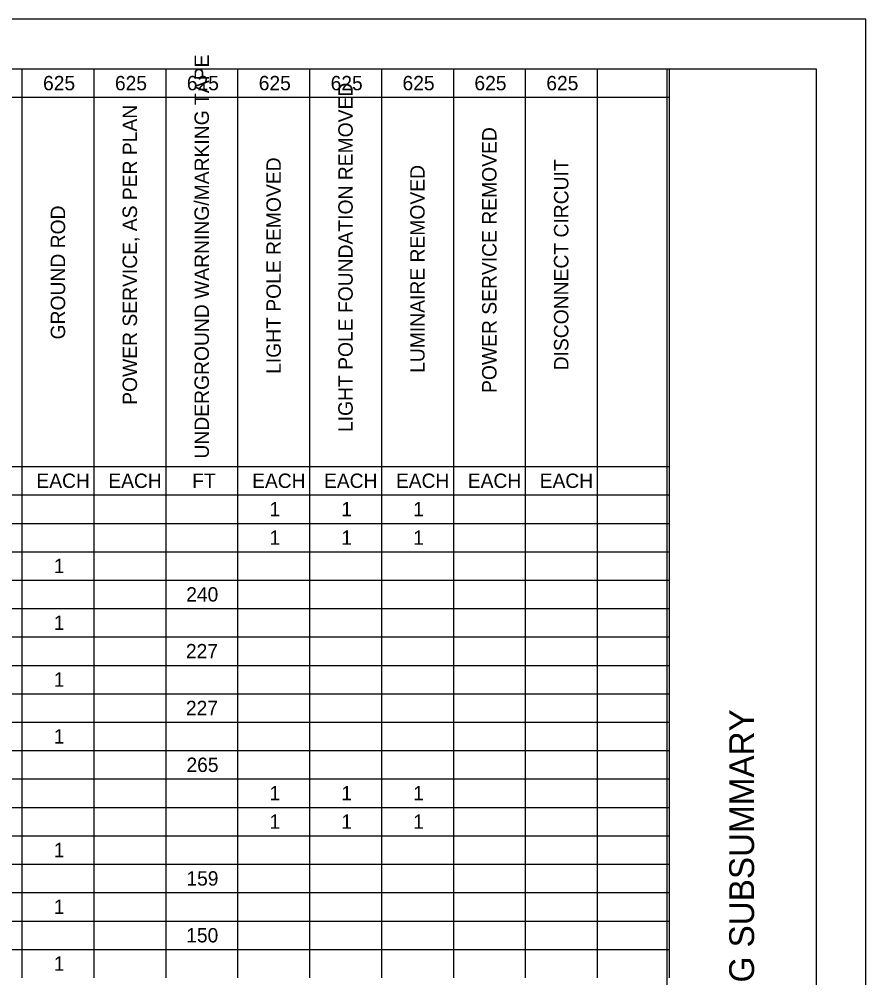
# Model space of a CAD drawing. Extents: x -1022.2 to -988.2, y -965.8 to -943.8.
# Drawn here: x -996.77 to -988.25, y -953.43 to -943.79 of the extents above; entities that cross this region are included whole.
import ezdxf

# ---------------------------------------------------------------- set-up
doc = ezdxf.new("R2010")
doc.units = 0
for name, color, linetype in [('Default', 7, 'Continuous'), ('SH_Border', 7, 'Continuous'), ('SH_Cut_Line', 7, 'Continuous'), ('SH_Data', 7, 'Continuous')]:
    doc.layers.add(name, color=color, linetype=linetype)

msp = doc.modelspace()

# ---------------------------------------------------------------- linework, layer by layer
at = {"layer": 'Default'}
for p, q in [((-998.1912, -944.2862), (-996.0201, -944.2862)), ((-996.7438, -944.2862), (-996.7438, -944.5719)), ((-996.0201, -944.2862), (-995.2964, -944.2862)), ((-996.0201, -944.2862), (-996.0201, -944.5719)), ((-995.2964, -944.2862), (-994.5726, -944.2862)), ((-995.2964, -944.2862), (-995.2964, -944.5719)), ((-994.5726, -944.2862), (-992.4015, -944.2862)), ((-994.5726, -944.2862), (-994.5726, -944.5719)), ((-993.8489, -944.2862), (-993.8489, -944.5719)), ((-993.1252, -944.2862), (-993.1252, -944.5719)), ((-992.4015, -944.2862), (-991.6778, -944.2862)), ((-992.4015, -944.2862), (-992.4015, -944.5719)), ((-991.6778, -944.2862), (-990.9541, -944.2862)), ((-991.6778, -944.2862), (-991.6778, -944.5719)), ((-990.9541, -944.2862), (-990.2303, -944.2862)), ((-990.9541, -944.2862), (-990.9541, -944.5719)), ((-990.2303, -944.2862), (-990.2303, -944.5719)), ((-998.1912, -944.5719), (-996.0201, -944.5719)), ((-996.7438, -944.5719), (-996.7438, -944.8577)), ((-996.0201, -944.5719), (-995.2964, -944.5719)), ((-996.0201, -944.5719), (-996.0201, -944.8577)), ((-995.2964, -944.5719), (-994.5726, -944.5719)), ((-995.2964, -944.5719), (-995.2964, -944.8577)), ((-994.5726, -944.5719), (-992.4015, -944.5719)), ((-994.5726, -944.5719), (-994.5726, -944.8577)), ((-993.8489, -944.5719), (-993.8489, -944.8577)), ((-993.1252, -944.5719), (-993.1252, -944.8577)), ((-992.4015, -944.5719), (-991.6778, -944.5719)), ((-992.4015, -944.5719), (-992.4015, -944.8577)), ((-991.6778, -944.5719), (-990.9541, -944.5719)), ((-991.6778, -944.5719), (-991.6778, -944.8577)), ((-990.9541, -944.5719), (-990.2303, -944.5719)), ((-990.9541, -944.5719), (-990.9541, -944.8577)), ((-990.2303, -944.5719), (-990.2303, -944.8577)), ((-996.7438, -944.8577), (-996.7438, -945.1434)), ((-996.0201, -944.8577), (-996.0201, -945.1434)), ((-995.2964, -944.8577), (-995.2964, -945.1434)), ((-994.5726, -944.8577), (-994.5726, -945.1434)), ((-993.8489, -944.8577), (-993.8489, -945.1434)), ((-993.1252, -944.8577), (-993.1252, -945.1434)), ((-992.4015, -944.8577), (-992.4015, -945.1434)), ((-991.6778, -944.8577), (-991.6778, -945.1434)), ((-990.9541, -944.8577), (-990.9541, -945.1434)), ((-990.2303, -944.8577), (-990.2303, -945.1434)), ((-996.7438, -945.1434), (-996.7438, -945.4292)), ((-996.0201, -945.1434), (-996.0201, -945.4292)), ((-995.2964, -945.1434), (-995.2964, -945.4292)), ((-994.5726, -945.1434), (-994.5726, -945.4292)), ((-993.8489, -945.1434), (-993.8489, -945.4292)), ((-993.1252, -945.1434), (-993.1252, -945.4292)), ((-992.4015, -945.1434), (-992.4015, -945.4292)), ((-991.6778, -945.1434), (-991.6778, -945.4292)), ((-990.9541, -945.1434), (-990.9541, -945.4292)), ((-990.2303, -945.1434), (-990.2303, -945.4292)), ((-996.7438, -945.4292), (-996.7438, -945.7149)), ((-996.0201, -945.4292), (-996.0201, -945.7149)), ((-995.2964, -945.4292), (-995.2964, -945.7149)), ((-994.5726, -945.4292), (-994.5726, -945.7149)), ((-993.8489, -945.4292), (-993.8489, -945.7149)), ((-993.1252, -945.4292), (-993.1252, -945.7149)), ((-992.4015, -945.4292), (-992.4015, -945.7149)), ((-991.6778, -945.4292), (-991.6778, -945.7149)), ((-990.9541, -945.4292), (-990.9541, -945.7149)), ((-990.2303, -945.4292), (-990.2303, -945.7149)), ((-996.7438, -945.7149), (-996.7438, -946.0006)), ((-996.0201, -945.7149), (-996.0201, -946.0006)), ((-995.2964, -945.7149), (-995.2964, -946.0006)), ((-994.5726, -945.7149), (-994.5726, -946.0006)), ((-993.8489, -945.7149), (-993.8489, -946.0006)), ((-993.1252, -945.7149), (-993.1252, -946.0006)), ((-992.4015, -945.7149), (-992.4015, -946.0006)), ((-991.6778, -945.7149), (-991.6778, -946.0006)), ((-990.9541, -945.7149), (-990.9541, -946.0006)), ((-990.2303, -945.7149), (-990.2303, -946.0006)), ((-996.7438, -946.0006), (-996.7438, -946.2864)), ((-996.0201, -946.0006), (-996.0201, -946.2864)), ((-995.2964, -946.0006), (-995.2964, -946.2864)), ((-994.5726, -946.0006), (-994.5726, -946.2864)), ((-993.8489, -946.0006), (-993.8489, -946.2864)), ((-993.1252, -946.0006), (-993.1252, -946.2864)), ((-992.4015, -946.0006), (-992.4015, -946.2864)), ((-991.6778, -946.0006), (-991.6778, -946.2864)), ((-990.9541, -946.0006), (-990.9541, -946.2864)), ((-990.2303, -946.0006), (-990.2303, -946.2864)), ((-996.7438, -946.2864), (-996.7438, -946.8578)), ((-996.0201, -946.2864), (-996.0201, -946.8578)), ((-995.2964, -946.2864), (-995.2964, -946.8578)), ((-994.5726, -946.2864), (-994.5726, -946.8578)), ((-993.8489, -946.2864), (-993.8489, -946.8578)), ((-993.1252, -946.2864), (-993.1252, -946.8578)), ((-992.4015, -946.2864), (-992.4015, -946.8578)), ((-991.6778, -946.2864), (-991.6778, -946.8578)), ((-990.9541, -946.2864), (-990.9541, -946.8578)), ((-990.2303, -946.2864), (-990.2303, -946.8578)), ((-996.7438, -946.8578), (-996.7438, -947.7151)), ((-996.0201, -946.8578), (-996.0201, -947.7151)), ((-995.2964, -946.8578), (-995.2964, -947.7151)), ((-994.5726, -946.8578), (-994.5726, -947.7151)), ((-993.8489, -946.8578), (-993.8489, -947.7151)), ((-993.1252, -946.8578), (-993.1252, -947.7151)), ((-992.4015, -946.8578), (-992.4015, -947.7151)), ((-991.6778, -946.8578), (-991.6778, -947.7151)), ((-990.9541, -946.8578), (-990.9541, -947.7151)), ((-990.2303, -946.8578), (-990.2303, -947.7151)), ((-996.7438, -947.7151), (-996.7438, -948.0008)), ((-996.0201, -947.7151), (-996.0201, -948.0008)), ((-995.2964, -947.7151), (-995.2964, -948.0008)), ((-994.5726, -947.7151), (-994.5726, -948.0008)), ((-993.8489, -947.7151), (-993.8489, -948.0008)), ((-993.1252, -947.7151), (-993.1252, -948.0008)), ((-992.4015, -947.7151), (-992.4015, -948.0008)), ((-991.6778, -947.7151), (-991.6778, -948.0008)), ((-990.9541, -947.7151), (-990.9541, -948.0008)), ((-990.2303, -947.7151), (-990.2303, -948.0008)), ((-996.7438, -948.0008), (-996.7438, -948.5723)), ((-996.0201, -948.0008), (-996.0201, -948.5723)), ((-995.2964, -948.0008), (-995.2964, -948.5723)), ((-994.5726, -948.0008), (-994.5726, -948.5723)), ((-993.8489, -948.0008), (-993.8489, -948.5723)), ((-993.1252, -948.0008), (-993.1252, -948.5723)), ((-992.4015, -948.0008), (-992.4015, -948.5723)), ((-991.6778, -948.0008), (-991.6778, -948.5723)), ((-990.9541, -948.0008), (-990.9541, -948.5723)), ((-990.2303, -948.0008), (-990.2303, -948.5723)), ((-998.1912, -948.2865), (-996.0201, -948.2865)), ((-996.0201, -948.2865), (-995.2964, -948.2865)), ((-995.2964, -948.2865), (-994.5726, -948.2865)), ((-994.5726, -948.2865), (-992.4015, -948.2865)), ((-992.4015, -948.2865), (-991.6778, -948.2865)), ((-991.6778, -948.2865), (-990.9541, -948.2865)), ((-990.9541, -948.2865), (-990.2303, -948.2865)), ((-998.1912, -948.5723), (-996.0201, -948.5723)), ((-996.7438, -948.5723), (-996.7438, -948.858)), ((-996.0201, -948.5723), (-995.2964, -948.5723)), ((-996.0201, -948.5723), (-996.0201, -948.858)), ((-995.2964, -948.5723), (-994.5726, -948.5723)), ((-995.2964, -948.5723), (-995.2964, -948.858)), ((-994.5726, -948.5723), (-992.4015, -948.5723)), ((-994.5726, -948.5723), (-994.5726, -948.858)), ((-993.8489, -948.5723), (-993.8489, -948.858)), ((-993.1252, -948.5723), (-993.1252, -948.858)), ((-992.4015, -948.5723), (-991.6778, -948.5723)), ((-992.4015, -948.5723), (-992.4015, -948.858)), ((-991.6778, -948.5723), (-990.9541, -948.5723)), ((-991.6778, -948.5723), (-991.6778, -948.858)), ((-990.9541, -948.5723), (-990.2303, -948.5723)), ((-990.9541, -948.5723), (-990.9541, -948.858)), ((-990.2303, -948.5723), (-990.2303, -948.858)), ((-998.1912, -948.858), (-996.0201, -948.858)), ((-996.7438, -948.858), (-996.7438, -950.001)), ((-996.0201, -948.858), (-995.2964, -948.858)), ((-996.0201, -948.858), (-996.0201, -950.001)), ((-995.2964, -948.858), (-994.5726, -948.858)), ((-995.2964, -948.858), (-995.2964, -950.001)), ((-994.5726, -948.858), (-992.4015, -948.858)), ((-994.5726, -948.858), (-994.5726, -950.001)), ((-993.8489, -948.858), (-993.8489, -950.001)), ((-993.1252, -948.858), (-993.1252, -950.001)), ((-992.4015, -948.858), (-991.6778, -948.858)), ((-992.4015, -948.858), (-992.4015, -950.001)), ((-991.6778, -948.858), (-990.9541, -948.858)), ((-991.6778, -948.858), (-991.6778, -950.001)), ((-990.9541, -948.858), (-990.2303, -948.858)), ((-990.9541, -948.858), (-990.9541, -950.001)), ((-990.2303, -948.858), (-990.2303, -950.001)), ((-998.1912, -949.1437), (-996.0201, -949.1437)), ((-996.0201, -949.1437), (-995.2964, -949.1437)), ((-995.2964, -949.1437), (-994.5726, -949.1437)), ((-994.5726, -949.1437), (-992.4015, -949.1437)), ((-992.4015, -949.1437), (-991.6778, -949.1437)), ((-991.6778, -949.1437), (-990.9541, -949.1437)), ((-990.9541, -949.1437), (-990.2303, -949.1437)), ((-998.1912, -949.4295), (-996.0201, -949.4295)), ((-996.0201, -949.4295), (-995.2964, -949.4295)), ((-995.2964, -949.4295), (-994.5726, -949.4295)), ((-994.5726, -949.4295), (-992.4015, -949.4295)), ((-992.4015, -949.4295), (-991.6778, -949.4295)), ((-991.6778, -949.4295), (-990.9541, -949.4295)), ((-990.9541, -949.4295), (-990.2303, -949.4295)), ((-998.1912, -949.7152), (-996.0201, -949.7152)), ((-996.0201, -949.7152), (-995.2964, -949.7152)), ((-995.2964, -949.7152), (-994.5726, -949.7152)), ((-994.5726, -949.7152), (-992.4015, -949.7152)), ((-992.4015, -949.7152), (-991.6778, -949.7152)), ((-991.6778, -949.7152), (-990.9541, -949.7152)), ((-990.9541, -949.7152), (-990.2303, -949.7152)), ((-998.1912, -950.001), (-996.0201, -950.001)), ((-996.7438, -950.001), (-996.7438, -950.2867)), ((-996.0201, -950.001), (-995.2964, -950.001)), ((-996.0201, -950.001), (-996.0201, -950.2867)), ((-995.2964, -950.001), (-994.5726, -950.001)), ((-995.2964, -950.001), (-995.2964, -950.2867)), ((-994.5726, -950.001), (-992.4015, -950.001)), ((-994.5726, -950.001), (-994.5726, -950.2867)), ((-993.8489, -950.001), (-993.8489, -950.2867)), ((-993.1252, -950.001), (-993.1252, -950.2867)), ((-992.4015, -950.001), (-991.6778, -950.001)), ((-992.4015, -950.001), (-992.4015, -950.2867)), ((-991.6778, -950.001), (-990.9541, -950.001)), ((-991.6778, -950.001), (-991.6778, -950.2867)), ((-990.9541, -950.001), (-990.2303, -950.001)), ((-990.9541, -950.001), (-990.9541, -950.2867)), ((-990.2303, -950.001), (-990.2303, -950.2867)), ((-998.1912, -950.2867), (-996.0201, -950.2867)), ((-996.7438, -950.2867), (-996.7438, -950.8582)), ((-996.0201, -950.2867), (-995.2964, -950.2867)), ((-996.0201, -950.2867), (-996.0201, -950.8582)), ((-995.2964, -950.2867), (-994.5726, -950.2867)), ((-995.2964, -950.2867), (-995.2964, -950.8582)), ((-994.5726, -950.2867), (-992.4015, -950.2867)), ((-994.5726, -950.2867), (-994.5726, -950.8582)), ((-993.8489, -950.2867), (-993.8489, -950.8582)), ((-993.1252, -950.2867), (-993.1252, -950.8582)), ((-992.4015, -950.2867), (-991.6778, -950.2867)), ((-992.4015, -950.2867), (-992.4015, -950.8582)), ((-991.6778, -950.2867), (-990.9541, -950.2867)), ((-991.6778, -950.2867), (-991.6778, -950.8582)), ((-990.9541, -950.2867), (-990.2303, -950.2867)), ((-990.9541, -950.2867), (-990.9541, -950.8582)), ((-990.2303, -950.2867), (-990.2303, -950.8582)), ((-998.1912, -950.5724), (-996.0201, -950.5724)), ((-996.0201, -950.5724), (-995.2964, -950.5724)), ((-995.2964, -950.5724), (-994.5726, -950.5724)), ((-994.5726, -950.5724), (-992.4015, -950.5724)), ((-992.4015, -950.5724), (-991.6778, -950.5724)), ((-991.6778, -950.5724), (-990.9541, -950.5724)), ((-990.9541, -950.5724), (-990.2303, -950.5724)), ((-998.1912, -950.8582), (-996.0201, -950.8582)), ((-996.7438, -950.8582), (-996.7438, -951.4296)), ((-996.0201, -950.8582), (-995.2964, -950.8582)), ((-996.0201, -950.8582), (-996.0201, -951.4296)), ((-995.2964, -950.8582), (-994.5726, -950.8582)), ((-995.2964, -950.8582), (-995.2964, -951.4296)), ((-994.5726, -950.8582), (-992.4015, -950.8582)), ((-994.5726, -950.8582), (-994.5726, -951.4296)), ((-993.8489, -950.8582), (-993.8489, -951.4296)), ((-993.1252, -950.8582), (-993.1252, -951.4296)), ((-992.4015, -950.8582), (-991.6778, -950.8582)), ((-992.4015, -950.8582), (-992.4015, -951.4296)), ((-991.6778, -950.8582), (-990.9541, -950.8582)), ((-991.6778, -950.8582), (-991.6778, -951.4296)), ((-990.9541, -950.8582), (-990.2303, -950.8582)), ((-990.9541, -950.8582), (-990.9541, -951.4296)), ((-990.2303, -950.8582), (-990.2303, -951.4296)), ((-998.1912, -951.1439), (-996.0201, -951.1439)), ((-996.0201, -951.1439), (-995.2964, -951.1439)), ((-995.2964, -951.1439), (-994.5726, -951.1439)), ((-994.5726, -951.1439), (-992.4015, -951.1439)), ((-992.4015, -951.1439), (-991.6778, -951.1439)), ((-991.6778, -951.1439), (-990.9541, -951.1439)), ((-990.9541, -951.1439), (-990.2303, -951.1439)), ((-998.1912, -951.4296), (-996.0201, -951.4296)), ((-996.7438, -951.4296), (-996.7438, -951.7154)), ((-996.0201, -951.4296), (-995.2964, -951.4296)), ((-996.0201, -951.4296), (-996.0201, -951.7154)), ((-995.2964, -951.4296), (-994.5726, -951.4296)), ((-995.2964, -951.4296), (-995.2964, -951.7154)), ((-994.5726, -951.4296), (-992.4015, -951.4296)), ((-994.5726, -951.4296), (-994.5726, -951.7154)), ((-993.8489, -951.4296), (-993.8489, -951.7154)), ((-993.1252, -951.4296), (-993.1252, -951.7154)), ((-992.4015, -951.4296), (-991.6778, -951.4296)), ((-992.4015, -951.4296), (-992.4015, -951.7154)), ((-991.6778, -951.4296), (-990.9541, -951.4296)), ((-991.6778, -951.4296), (-991.6778, -951.7154)), ((-990.9541, -951.4296), (-990.2303, -951.4296)), ((-990.9541, -951.4296), (-990.9541, -951.7154)), ((-990.2303, -951.4296), (-990.2303, -951.7154)), ((-998.1912, -951.7154), (-996.0201, -951.7154)), ((-996.7438, -951.7154), (-996.7438, -952.2869)), ((-996.0201, -951.7154), (-995.2964, -951.7154)), ((-996.0201, -951.7154), (-996.0201, -952.2869)), ((-995.2964, -951.7154), (-994.5726, -951.7154)), ((-995.2964, -951.7154), (-995.2964, -952.2869)), ((-994.5726, -951.7154), (-992.4015, -951.7154)), ((-994.5726, -951.7154), (-994.5726, -952.2869)), ((-993.8489, -951.7154), (-993.8489, -952.2869)), ((-993.1252, -951.7154), (-993.1252, -952.2869)), ((-992.4015, -951.7154), (-991.6778, -951.7154)), ((-992.4015, -951.7154), (-992.4015, -952.2869)), ((-991.6778, -951.7154), (-990.9541, -951.7154)), ((-991.6778, -951.7154), (-991.6778, -952.2869)), ((-990.9541, -951.7154), (-990.2303, -951.7154)), ((-990.9541, -951.7154), (-990.9541, -952.2869)), ((-990.2303, -951.7154), (-990.2303, -952.2869)), ((-998.1912, -952.0011), (-996.0201, -952.0011)), ((-996.0201, -952.0011), (-995.2964, -952.0011)), ((-995.2964, -952.0011), (-994.5726, -952.0011)), ((-994.5726, -952.0011), (-992.4015, -952.0011)), ((-992.4015, -952.0011), (-991.6778, -952.0011)), ((-991.6778, -952.0011), (-990.9541, -952.0011)), ((-990.9541, -952.0011), (-990.2303, -952.0011)), ((-998.1912, -952.2869), (-996.0201, -952.2869)), ((-996.7438, -952.2869), (-996.7438, -952.5726)), ((-996.0201, -952.2869), (-995.2964, -952.2869)), ((-996.0201, -952.2869), (-996.0201, -952.5726)), ((-995.2964, -952.2869), (-994.5726, -952.2869)), ((-995.2964, -952.2869), (-995.2964, -952.5726)), ((-994.5726, -952.2869), (-992.4015, -952.2869)), ((-994.5726, -952.2869), (-994.5726, -952.5726)), ((-993.8489, -952.2869), (-993.8489, -952.5726)), ((-993.1252, -952.2869), (-993.1252, -952.5726)), ((-992.4015, -952.2869), (-991.6778, -952.2869)), ((-992.4015, -952.2869), (-992.4015, -952.5726)), ((-991.6778, -952.2869), (-990.9541, -952.2869)), ((-991.6778, -952.2869), (-991.6778, -952.5726)), ((-990.9541, -952.2869), (-990.2303, -952.2869)), ((-990.9541, -952.2869), (-990.9541, -952.5726)), ((-990.2303, -952.2869), (-990.2303, -952.5726)), ((-998.1912, -952.5726), (-996.0201, -952.5726)), ((-996.7438, -952.5726), (-996.7438, -953.4298)), ((-996.0201, -952.5726), (-995.2964, -952.5726)), ((-996.0201, -952.5726), (-996.0201, -953.4298)), ((-995.2964, -952.5726), (-994.5726, -952.5726)), ((-995.2964, -952.5726), (-995.2964, -953.4298)), ((-994.5726, -952.5726), (-992.4015, -952.5726)), ((-994.5726, -952.5726), (-994.5726, -953.4298)), ((-993.8489, -952.5726), (-993.8489, -953.4298)), ((-993.1252, -952.5726), (-993.1252, -953.4298)), ((-992.4015, -952.5726), (-991.6778, -952.5726)), ((-992.4015, -952.5726), (-992.4015, -953.4298)), ((-991.6778, -952.5726), (-990.9541, -952.5726)), ((-991.6778, -952.5726), (-991.6778, -953.4298)), ((-990.9541, -952.5726), (-990.2303, -952.5726)), ((-990.9541, -952.5726), (-990.9541, -953.4298)), ((-990.2303, -952.5726), (-990.2303, -953.4298)), ((-998.1912, -952.8583), (-996.0201, -952.8583)), ((-996.0201, -952.8583), (-995.2964, -952.8583)), ((-995.2964, -952.8583), (-994.5726, -952.8583)), ((-994.5726, -952.8583), (-992.4015, -952.8583)), ((-992.4015, -952.8583), (-991.6778, -952.8583)), ((-991.6778, -952.8583), (-990.9541, -952.8583)), ((-990.9541, -952.8583), (-990.2303, -952.8583)), ((-998.1912, -953.1441), (-996.0201, -953.1441)), ((-996.0201, -953.1441), (-995.2964, -953.1441)), ((-995.2964, -953.1441), (-994.5726, -953.1441)), ((-994.5726, -953.1441), (-992.4015, -953.1441)), ((-992.4015, -953.1441), (-991.6778, -953.1441)), ((-991.6778, -953.1441), (-990.9541, -953.1441)), ((-990.9541, -953.1441), (-990.2303, -953.1441))]:
    msp.add_line(p, q, dxfattribs=at)
at = {"layer": 'SH_Border'}
msp.add_line((-990.2494, -965.2862), (-990.2494, -944.2862), dxfattribs=at)
msp.add_lwpolyline([(-1020.7494, -944.2862), (-988.7494, -944.2862), (-988.7494, -965.2862), (-1020.7494, -965.2862)], close=True, dxfattribs=at)
at = {"layer": 'SH_Cut_Line'}
msp.add_lwpolyline([(-1022.2494, -965.7862), (-988.2494, -965.7862), (-988.2494, -943.7862), (-1022.2494, -943.7862)], close=True, dxfattribs=at)

# ---------------------------------------------------------------- texts
at = {"layer": 'Default'}
for s, height, p in [('UNDERGROUND WARNING/MARKING TAPE', 0.145085, (-994.862, -948.2062)), ('LIGHT POLE FOUNDATION REMOVED', 0.145085, (-993.4145, -947.9393)), ('POWER SERVICE, AS PER PLAN', 0.145085, (-995.5857, -947.6659)), ('POWER SERVICE REMOVED', 0.145085, (-991.9671, -947.5462)), ('LIGHT POLE REMOVED', 0.145085, (-994.1382, -947.3543)), ('LUMINAIRE REMOVED', 0.145085, (-992.6908, -947.3442)), ('DISCONNECT CIRCUIT', 0.145085, (-991.2434, -947.3191)), ('GROUND ROD', 0.14508, (-996.3094, -947.0078))]:
    msp.add_text(s, height=height, rotation=90, dxfattribs=at).set_placement(p)
for s, height, p in [('625', 0.14457, (-996.5315, -944.5014)), ('625', 0.14457, (-995.8078, -944.5014)), ('625', 0.14457, (-995.0841, -944.5014)), ('625', 0.14457, (-994.3604, -944.5014)), ('625', 0.14457, (-993.6366, -944.5014)), ('625', 0.14457, (-992.9129, -944.5014)), ('625', 0.14457, (-992.1892, -944.5014)), ('625', 0.14457, (-991.4655, -944.5014)), ('EACH', 0.14457, (-996.598, -948.5017)), ('EACH', 0.14457, (-995.8743, -948.5017)), ('EACH', 0.14457, (-994.4268, -948.5017)), ('EACH', 0.14457, (-993.7031, -948.5017)), ('EACH', 0.14457, (-992.9794, -948.5017)), ('EACH', 0.14457, (-992.2557, -948.5017)), ('EACH', 0.14457, (-991.5319, -948.5017)), ('FT', 0.14457, (-995.0307, -948.5017)), ('1', 0.1446, (-994.2528, -948.7874)), ('1', 0.1446, (-993.5291, -948.7874)), ('1', 0.1446, (-992.8053, -948.7874)), ('1', 0.1446, (-994.2528, -949.0732)), ('1', 0.1446, (-993.5291, -949.0732)), ('1', 0.1446, (-992.8053, -949.0732)), ('1', 0.1446, (-996.4239, -949.3589)), ('240', 0.14457, (-995.0902, -949.6446)), ('1', 0.1446, (-996.4239, -949.9304)), ('227', 0.14457, (-995.0936, -950.2161)), ('1', 0.1446, (-996.4239, -950.5018)), ('227', 0.14457, (-995.0936, -950.7876)), ('1', 0.1446, (-996.4239, -951.0733)), ('265', 0.14457, (-995.0879, -951.3591)), ('1', 0.1446, (-994.2528, -951.6448)), ('1', 0.1446, (-993.5291, -951.6448)), ('1', 0.1446, (-992.8053, -951.6448)), ('1', 0.1446, (-994.2528, -951.9305)), ('1', 0.1446, (-993.5291, -951.9305)), ('1', 0.1446, (-992.8053, -951.9305)), ('1', 0.1446, (-996.4239, -952.2163)), ('159', 0.14457, (-995.0886, -952.502)), ('1', 0.1446, (-996.4239, -952.7877)), ('150', 0.14457, (-995.0902, -953.0735)), ('1', 0.1446, (-996.4239, -953.3592))]:
    msp.add_text(s, height=height, dxfattribs=at).set_placement(p)
at = {"layer": 'SH_Data'}
msp.add_text('LIGHTING SUBSUMMARY', height=0.25, rotation=90, dxfattribs=at).set_placement((-989.3744, -954.7958))

doc.saveas('drawing.dxf')
